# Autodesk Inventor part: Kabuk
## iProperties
Company: Autodesk, Inc.
Shininess: 64.0
Length Units: 11269
Angle Units: 11279
Time Units: 11290
Mass Units: 11283
Length Display Precision: 3
Angle Display Precision: 2
Compacted: True
Part Number: Kabuk
Document SubType Name: Modeling
Created: 2003-12
Catalog Web Link: www.autodesk.com
Vendor: Autodesk, Inc.
Designer: Administrator
Manufacturer: Standard
Standards Organization: Custom
Density: 1 g/cm^3
Density: 0.0
Volumn: 0.0
Area: 0.0
PropertySet Name: Model Information
Control State: 0
Master: False
Checked Out: False
Author: Administrator
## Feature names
1. Revolution1
2. Extrusion1
3. Fillet3
4. Hole1
5. Hole2
6. Split1
7. Split2
8. Split3
9. Split4
10. Split5
11. Split6
12. Split7
13. Split8
14. Split9
15. Split10
16. Split11
17. Split12
18. Split13
19. Split14
20. Split15
21. Split16
22. Split17
23. Split18
24. Split19
25. Split20
